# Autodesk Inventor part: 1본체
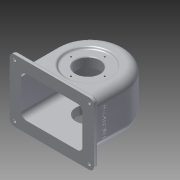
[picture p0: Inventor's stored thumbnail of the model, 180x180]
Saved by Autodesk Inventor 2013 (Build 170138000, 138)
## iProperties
Created: 2016-01
Part Number: 1본체
Material: 알루미늄 6061
Document SubType Name: Modeling
Designer: Administrator
Density: 2.71 g/cm^3
Mass: 809.754 g
Surface Area: 999.207 cm^2
Volume: 298.802 cm^3
Author: Administrator
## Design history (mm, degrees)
sketch "스케치1"
  geometry: L1 (-57, 0)-(-57, -64); L2 (57, 0)-(57, -64); L3 (-57, -64)-(57, -64); A1 r 57 centre (0, 0) between (57, 0) and (-57, 0); 1 further point
  constraints: 6 end point, 2 point on circle, 2 tangent, 1 centre point, 1 coincident, 1 parallel, 1 perpendicular, 1 vertical
  dimensions: "d0" = 114 diameter of A1; "d1" = 64 distance from line of L3 point (0, 0)
extrude "돌출1" new body sketch "스케치1" distance "d2" = 77; taper "d3" = 0 deg
sketch "스케치2"
  geometry: L1 (0, 0)-(114, 0) reference; L2 (114, 0)-(114, 77) reference; L3 (0, 77)-(114, 77) reference; L4 (0, 0)-(0, 77) reference; L5 (-13, -13.5)-(127, -13.5); L6 (127, -13.5)-(127, 90.5); L7 (127, 90.5)-(-13, 90.5); L8 (-13, 90.5)-(-13, -13.5); L9 (0, 38.5)-(114, 38.5); L10 (57, 0)-(57, 77)
  constraints: 12 end point, 3 midpoint, 2 parallel, 1 horizontal, 1 perpendicular
  dimensions: "d4" = 70 distance between parallel lines of L10 L8; "d6" = 140 distance between parallel lines of L6 L8; "d7" = 52 distance between parallel lines of L9 L7; "d8" = 104 distance between parallel lines of L5 L7
extrude "돌출2" join sketch "스케치2" distance "d9" = 7; taper "d10" = 0 deg
node "작업 평면1"
sketch "스케치3"
  geometry: L1 (19, 64)-(19, 0); L2 (121, 64)-(121, 0); L3 (19, 0)-(121, 0); L4 (0, 0)-(140, 0) reference; A1 r 51 centre (70, 64) between (121, 64) and (19, 64); 1 further point
  constraints: 6 end point, 2 point on circle, 2 tangent, 1 centre point, 1 coincident, 1 collinear, 1 parallel, 1 perpendicular, 1 point on line, 1 vertical
  dimensions: "d11" = 102 diameter of A1
extrude "돌출3" cut sketch "스케치3" stored distance "d12" = 67; taper "d13" = 0 deg
sketch "스케치4"
  geometry: L1 (-4, 77)-(-4, 58); L2 (-64, 90.5)-(-64, -13.5) reference; L3 (51, 72)-(0, 72) reference; L4 (57, 77)-(0, 77) reference; L5 (0, 72)-(-64, 72) reference; L6 (0, 77)-(-57, 77) reference; L7 (37.426, 74)-(-4, 74); L8 (24, 58)-(-4, 58); L9 (24, 58)-(37.426, 74); 1 further point
  constraints: 8 end point, 2 point on line, 1 parallel, 1 vertical
  dimensions: "d14" = 60 distance between parallel lines of L2 L1; "d16" = 3 distance between parallel lines of L6 L7; "d17" = 16 distance between parallel lines of L7 L8; "d20" = 28 distance of L8.start L1.end; "d21" = 50 deg angle of L8 L9
revolve "회전1" sketch "스케치4" stored, may be unused: angle "d22" = 90 deg
node "작업 평면2"
sketch "스케치8"
  geometry: L1 (140, 104)-(140, 0) reference; L2 (0, 104)-(140, 104) reference; L3 (70, 104)-(70, 25.33); L4 (140, 52)-(7.319, 52); C1 r 6 at (70, 52); 1 further point
  constraints: 4 end point, 2 midpoint, 2 perpendicular, 2 point on line, 1 centre point
  dimensions: "d33" = 12 diameter of C1
extrude "돌출6" join sketch "스케치8" stored distance "d34" = 10; taper "d35" = 0 deg
sketch "스케치9"
  geometry: L1 (0, 0)-(0, -77) reference; L2 (-13, 13.5)-(-13, -90.5) reference; L3 (127, -90.5)-(127, 13.5) reference; L4 (-5, 21.847)-(-5, -103.111); L5 (-31.881, 5.5)-(14.035, 5.5); L6 (0, -38.5)-(14.035, -38.5); C1 r 2.5 at (-5, 5.5); 1 further point
  constraints: 6 end point, 2 parallel, 2 point on line, 1 centre point, 1 midpoint, 1 perpendicular
  dimensions: "d36" = 8 distance between parallel lines of L2 L4; "d37" = 44 distance between parallel lines of L6 L5; "d38" = 5 diameter of C1
extrude "돌출7" cut sketch "스케치9" distance "d39" = 10; taper "d40" = 0 deg
sketch "스케치10"
  geometry: L1 (0, 0)-(0, -77) reference; L2 (127, -90.5)-(127, 13.5) reference; L3 (0, -38.5)-(-24.213, -38.5); C1 r 2.5 at (-5, 5.5) reference; C2 r 2.5 at (-5, -38.5); 1 further point
  constraints: 2 end point, 1 centre point, 1 midpoint, 1 perpendicular, 1 point on line, 1 vertical alignment
  dimensions: "d41" = 5 diameter of C2
extrude "돌출8" cut sketch "스케치10" distance "d42" = 10; taper "d43" = 0 deg
node "작업 평면3"
sketch "스케치12"
  geometry: C1 r 28 at (0, 0) reference; C2 r 20 at (0, 0); 1 further point
  constraints: 1 centre point, 1 coincident
  dimensions: "d45" = 40 diameter of C2
extrude "돌출9" cut sketch "스케치12" stored distance "d46" = 10; taper "d47" = 0 deg
sketch "스케치13"
  geometry: L1 (90.5, 97.416)-(87.5, 94.899); L2 (85.5, 64)-(18.5, 64) reference; L3 (18.5, 64)-(18.5, 64) reference; L4 (18.5, 64)-(85.5, 64) reference; L5 (85.5, 64)-(85.5, 64) reference; L6 (85.5, 99.747)-(71.5, 88) reference; L7 (87.5, 94.899)-(87.5, 60); L8 (90.5, 80)-(90.5, 40) reference; L9 (90.5, 97.416)-(90.5, 60); L10 (87.5, 60)-(90.5, 60); L11 (104, 0)-(0, 0) reference; 1 further point
  constraints: 8 end point, 2 perpendicular, 1 parallel, 1 point on line
  dimensions: "d48" = 5 distance between parallel lines of L1 L6; "d49" = 3 distance between parallel lines of L8 L7; "d50" = 60 distance between parallel lines of L11 L10
revolve "회전3" sketch "스케치13" stored, may be unused: angle "d51" = 90 deg
sketch "스케치14"
  geometry: C1 r 20 at (0, -4) reference; C2 r 31 at (0, -4)
  constraints: 1 centre point, 1 coincident
  dimensions: "d52" = 62 diameter of C2
extrude "돌출10" join sketch "스케치14" distance "d53" = 10; taper "d54" = 0 deg
sketch "스케치15" dims "d55" = 56
  geometry: L1 (0, 0)-(0, 39.671); C1 r 34.899 at (0, 0) reference; 3 further points
  constraints: 2 end point, 1 coincident, 1 point on line, 1 vertical, 1 vertical alignment, 2 other
hole "구멍1" sketch "스케치15" at (0, 28) diameter "d56" = 2.459; stored, may be unused: countersink angle "d60" = 90 deg, drill point angle "d62" = 118 deg; dims "d57" = 7, "d58" = 4, "d59" = 2, "d61" = 9
sketch "스케치16" dims "d66" = 48
  geometry: L1 (0, 0)-(0, 47.578); C1 r 31 at (0, 0) reference; 3 further points
  constraints: 2 end point, 1 coincident, 1 point on line, 1 vertical, 1 vertical alignment, 2 other
hole "구멍2" sketch "스케치16" at (0, 24) diameter "d67" = 2.459; stored, may be unused: countersink angle "d71" = 90 deg, drill point angle "d73" = 118 deg; dims "d68" = 6, "d69" = 4, "d70" = 2, "d72" = 8
sketch "스케치17"
  geometry: C1 r 6 at (0, 0) reference; 2 further points
  constraints: 1 coincident
hole "구멍3" sketch "스케치17" at (0, 0) diameter "d77" = 4.459; stored, may be unused: countersink angle "d81" = 90 deg, drill point angle "d83" = 118 deg; dims "d78" = 19, "d79" = 4, "d80" = 2, "d82" = 20
fillet "모깎기1" dims "d84" = 9
fillet "모깎기2" dims "d85" = 14
fillet "모깎기3" dims "d86" = 8
chamfer "모따기1" distance "d87" = 1; stored, may be unused: second distance "d88" = 2, angle "d89" = 45 deg
fillet "모깎기4" dims "d90" = 3
fillet "모깎기5" dims "d91" = 1
sketch "스케치18"
  geometry: L1 (-14, 0)-(-14, -56) reference; L2 (68.5, -64)-(-19.5, -64) reference; 2 further points
  constraints: 1 other
  dimensions: "d92" = 38.5 distance from line of L1 point (24.5, -34); "d93" = 30 distance from line of L2 point (24.5, -34)
feature "엠보싱1" sketch "스케치18" dims "d0" = 114, "d1" = 64, "d10" = 0, "d94" = 0.5, "d95" = 0
fillet "모깎기6" dims "d96" = 3
sketch "스케치20"
  geometry: C1 r 2.5 at (119, -38.5) reference; C2 r 2.5 at (-5, -38.5) reference; 1 further point
extrude "돌출12" join sketch "스케치20" distance "d100" = 7; taper "d101" = 0 deg
node "솔리드1"
mirror "대칭1"
mirror "대칭2"
pattern_circular "원형 패턴1" dims angle "d64" = 360 deg
pattern_circular "원형 패턴2" dims angle "d75" = 360 deg
node "투영된 루프1"
other parameters: "d32" = -127
